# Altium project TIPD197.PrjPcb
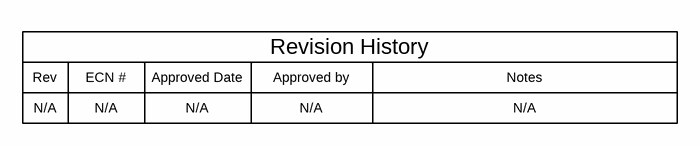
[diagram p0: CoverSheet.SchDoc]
TID: TIPD197; TechSupport: http://e2e.ti.com; SCH_Rev: 0; PRJ_Title: TI Precision Designs; PRJ_Number: TIPD197; PRJ_Engineer: Brian Pisani; PRJ_Customer: Precision Delta Sigma; PCB_Rev: 0; EVM_Orderable: N/A; CopyrightYear: 2015
3 sheets, 32 parts. Net scope: global (net labels, ports and power ports of the same name join across sheets).
Board file: TIPD197.PcbDoc
Sheets:
  CoverSheet.SchDoc
  TID_Hardware.SchDoc
  Front_End_and_ADC.SchDoc

## Sheet CoverSheet.SchDoc
size 431 x 279 mm; Date: Not shown in title block; ApprovedBy: Not shown in title block; CheckedBy: Not shown in title block; Author: Not shown in title block; CompanyName: Not shown in title block; Engineer: Not shown in title block; Organization: Not shown in title block; Address1: Not shown in title block; Address2: Not shown in title block; Address3: Not shown in title block; Address4: Not shown in title block; DocumentNumber: 1; Revision: Use project parameter SCH_Rev; SheetNumber: 1; SheetTotal: 3; PageSetup: Record=PageOptions¦CenterHorizontal=True¦CenterVertical=True¦PrintScale=1.00¦XCorrection=1.00¦YCorrection=1.00¦PrintKind=0¦BorderSize=5000000¦LeftOffset=0¦BottomOffset=0¦Orientation=2¦PaperLength=1000¦PaperWidth=1000¦Scale=100¦PaperSource=15¦PrintQuality=600¦MediaType=1¦DitherType=10¦PaperKind=Letter¦PrintScaleMode=1

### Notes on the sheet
- Rev
- N/A
- ECN #
- Approved Date
- Approved by
- Revision History
- Notes

## Sheet TID_Hardware.SchDoc
size 431 x 279 mm; Date: Not shown in title block; ApprovedBy: Not shown in title block; CheckedBy: Not shown in title block; Author: Not shown in title block; CompanyName: Not shown in title block; Engineer: Not shown in title block; Organization: Not shown in title block; Address1: Not shown in title block; Address2: Not shown in title block; Address3: Not shown in title block; Address4: Not shown in title block; DocumentNumber: 1; Revision: Use project parameter SCH_Rev; SheetNumber: 3; SheetTotal: 3; PageSetup: Record=PageOptions¦CenterHorizontal=True¦CenterVertical=True¦PrintScale=1.00¦XCorrection=1.00¦YCorrection=1.00¦PrintKind=0¦BorderSize=5000000¦LeftOffset=0¦BottomOffset=0¦Orientation=2¦PaperLength=1000¦PaperWidth=1000¦Scale=100¦PaperSource=15¦PrintQuality=600¦MediaType=1¦DitherType=10¦PaperKind=Letter¦PrintScaleMode=1
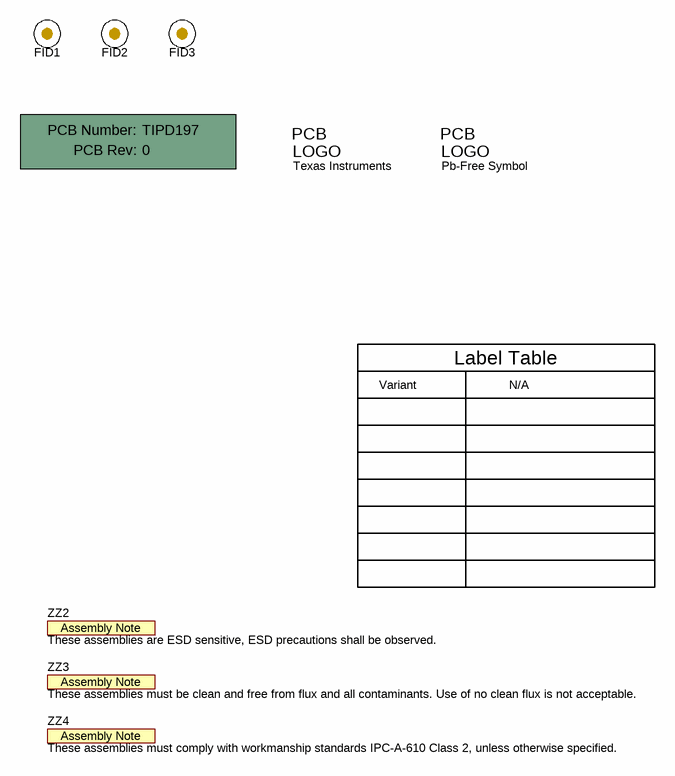
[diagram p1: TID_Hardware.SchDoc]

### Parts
!PCB  Printed Circuit Board  (value not drawn)  (mechanical)
FID1  Fiducial  [Fiducial10-20]  (value not drawn)
FID2  Fiducial  [Fiducial10-20]  (value not drawn)
FID3  Fiducial  [Fiducial10-20]  (value not drawn)
Logo1  Texas Instruments  [TI_Symbol_Overlay_Small]  (no BOM)
Logo2  Pb-Free Symbol  [Pb-Free_Overlay_Small]  (no BOM)
ZZ2  These assemblies are ESD sensitive, ESD precautions shall be observed.  [AssemblyNote]  (no BOM)
ZZ3  These assemblies must be clean and free from flux and all contaminants. Use of no clean flux is not acceptable.  [AssemblyNote]  (no BOM)
ZZ4  These assemblies must comply with workmanship standards IPC-A-610 Class 2, unless otherwise specified.  [AssemblyNote]  (no BOM)

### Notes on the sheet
- Variant
- Label Table
- N/A

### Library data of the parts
!PCB = PCB: Manufacturer: Any; PartNumber: TIPD197; SymbolCreator: a0412235
FID1-FID3 = Fiducial: Fiducial mark.  There is nothing to buy or mount.; SymbolCreator: codlsc
Logo1 = TI_Logo: Texas Instrument Corporate Signature; SymbolCreator: codlsc
Logo2 = Pb-Free: SymbolCreator: a0412235
ZZ2-ZZ4 = AssemblyNote: SymbolCreator: codlsc

## Sheet Front_End_and_ADC.SchDoc: Schematic for TIDCAP1
size 431 x 279 mm; Date: Not shown in title block; ApprovedBy: Not shown in title block; CheckedBy: Not shown in title block; Author: Not shown in title block; CompanyName: Not shown in title block; DrawnBy: Brian Pisani; Engineer: Brian Pisani; Organization: Not shown in title block; Address1: Not shown in title block; Address2: Not shown in title block; Address3: Not shown in title block; Address4: Not shown in title block; DocumentNumber: 1; Revision: Use project parameter SCH_Rev; SheetNumber: 2; SheetTotal: 3; PageSetup: Record=PageOptions¦CenterHorizontal=True¦CenterVertical=True¦PrintScale=1.00¦XCorrection=1.00¦YCorrection=1.00¦PrintKind=0¦BorderSize=5000000¦LeftOffset=0¦BottomOffset=0¦Orientation=2¦PaperLength=1000¦PaperWidth=1000¦Scale=100¦PaperSource=15¦PrintQuality=600¦MediaType=1¦DitherType=10¦PaperKind=Letter¦PrintScaleMode=1
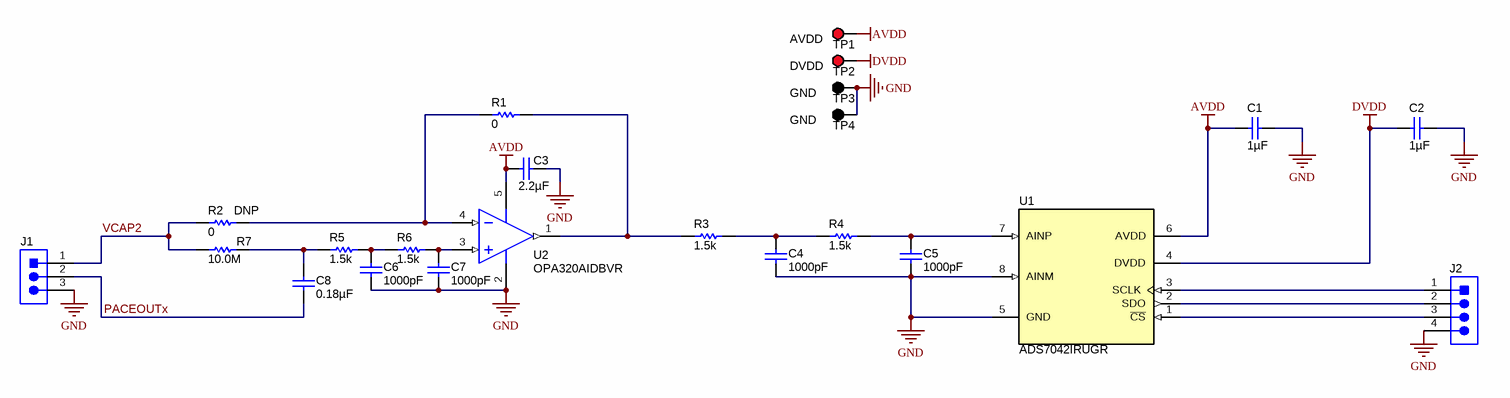
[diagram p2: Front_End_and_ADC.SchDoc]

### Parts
C1  ValueDisplayed: 1µF  [0402]  (hidden comment: C1005X5R1A105K050BB)
C2  ValueDisplayed: 1µF  [0402]  (hidden comment: C1005X5R1A105K050BB)
C3  ValueDisplayed: 2.2µF  [0402]  (hidden comment: C1005X5R1A225K050BC)
C4  ValueDisplayed: 1000pF  [0402]  (hidden comment: GRM155R72A102KA01D)
C5  ValueDisplayed: 1000pF  [0402]  (hidden comment: GRM155R72A102KA01D)
C6  ValueDisplayed: 1000pF  [0402]  (hidden comment: C1005C0G1E102J)
C7  ValueDisplayed: 1000pF  [0402]  (hidden comment: C1005C0G1E102J)
C8  ValueDisplayed: 0.18µF  [0402]  (hidden comment: GRM155R61A184KE19D)
J1  800-10-003-10-001000  [Mill-Max_800-10-003-10-001000]  (value not drawn)
J2  800-10-004-10-001000  [Mill-Max_800-10-004-10-001000]  (value not drawn)
R1  ValueDisplayed: 0  [0402]  (hidden comment: ERJ-2GE0R00X)
R2  DNP  ValueDisplayed: 0  [0402]
R3  ValueDisplayed: 1.5k  [0402]  (hidden comment: CRCW04021K50JNED)
R4  ValueDisplayed: 1.5k  [0402]  (hidden comment: CRCW04021K50JNED)
R5  ValueDisplayed: 1.5k  [0402]  (hidden comment: CRCW04021K50JNED)
R6  ValueDisplayed: 1.5k  [0402]  (hidden comment: CRCW04021K50JNED)
R7  ValueDisplayed: 10.0M  [0402]  (hidden comment: CRCW040210M0FKED)
TP1  AVDD  [Keystone5010]
TP2  DVDD  [Keystone5010]
TP3  GND  [Keystone5011]
TP4  GND  [Keystone5011]
U1  ADS7042IRUGR  [RUG0008A]
U2  OPA320AIDBVR  [DBV0005A_N]

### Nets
AVDD: C1.2 C3.2 TP1.1 U1.6(AVDD) U2.5(V+)
DVDD: C2.2 TP2.1 U1.4(DVDD)
GND: C1.1 C2.1 C3.1 C4.2 C5.2 C6.2 C7.2 J1.3 J2.4 TP3.1 TP4.1 U1.5(GND) U1.8(AINM) U2.2(V-)
PACEOUTx: C8.2 J1.2
VCAP2: J1.1 R2.1 R7.2
NetC4_1: C4.1 R3.2 R4.1
NetC5_1: C5.1 R4.2 U1.7(AINP)
NetC6_1: C6.1 R5.2 R6.1
NetC7_1: C7.1 R6.2 U2.3(IN+)
NetC8_1: C8.1 R5.1 R7.1
NetJ2_1: J2.1 U1.3(SCLK)
NetJ2_2: J2.2 U1.2(SDO)
NetJ2_3: J2.3 U1.1(~{CS})
NetR1_1: R1.1 R2.2 U2.4(IN-)
NetR1_2: R1.2 R3.1 U2.1(OUT)

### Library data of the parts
C1 C2 = C1005X5R1A105K050BB: CAP, CERM, 1 µF, 10 V, +/- 10%, X5R, 0402; Manufacturer: TDK; Polarized: N; CompType: Capacitor; Value: 1uF; U/M: EA; Cap_F: 0.000001; Tolerance_%: 10; Value1: Unknown; Value2: 10V; TaMin_C: -55; TaMax_C: 85
C3 = C1005X5R1A225K050BC: CAP, CERM, 2.2 µF, 10 V, +/- 10%, X5R, 0402; Manufacturer: TDK; Polarized: N; CompType: Capacitor; Value: 2.2uF; U/M: EA; Cap_F: 0.0000022; Tolerance_%: 10; Value1: Unknown; Value2: 10V; TaMin_C: -55; TaMax_C: 85
C4 C5 = GRM155R72A102KA01D: CAP, CERM, 1000 pF, 100 V, +/- 10%, X7R, 0402; Manufacturer: MuRata; Polarized: N; CompType: Capacitor; Value: 1000pF; U/M: EA; Cap_F: 0.000000001; Tolerance_%: 10; Value1: Unknown; VDC_V: 100; Value2: 100V; TaMin_C: -55; TaMax_C: 125
C6 C7 = C1005C0G1E102J: CAP, CERM, 1000 pF, 25 V, +/- 5%, C0G/NP0, 0402; Manufacturer: TDK; Polarized: N; CompType: Capacitor; Value: 1000pF; U/M: EA; Cap_F: 0.000000001; Tolerance_%: 5; Value1: Unknown; VDC_V: 25; Value2: 25V; TaMin_C: -55; TaMax_C: 125
C8 = GRM155R61A184KE19D: CAP, CERM, 0.18 µF, 10 V, +/- 10%, X5R, 0402; Manufacturer: MuRata; Polarized: N; CompType: Capacitor; Value: 0.18uF; U/M: EA; Cap_F: 0.00000018; Tolerance_%: 10; Value1: Unknown; Value2: 10V; TaMin_C: -55; TaMax_C: 85
J1 = 800-10-003-10-001000: Header, 100mil, 3x1, TH; Manufacturer: Mill-Max; SymbolCreator: a0799628; U/M: EA
J2 = 800-10-004-10-001000: Header, 100mil, 4x1, TH; Manufacturer: Mill-Max; SymbolCreator: a0412235; U/M: EA
R1 = ERJ-2GE0R00X: RES, 0, 5%, 0.063 W, 0402; Manufacturer: Panasonic; CompType: Resistor; Value: 0; Value_Code: 0000; Tolerance_%: 5; Power_W: 0.063; Value2: 0.063W; VDC_V: 50; TempCo: 600 ppm/C; EIA_Code: E24; U/M: EA
R2 = CRCW04020000Z0ED: RES, 0, 5%, 0.063 W, 0402; Manufacturer: Vishay-Dale; CompType: Resistor; Value: 0; Value_Code: 0000; Tolerance_%: 5; Power_W: 0.063; Value2: 0.063W; VDC_V: 50; TempCo: 200 ppm/C; EIA_Code: E24; U/M: EA
R3-R6 = CRCW04021K50JNED: RES, 1.5 k, 5%, 0.063 W, 0402; Manufacturer: Vishay-Dale; CompType: Resistor; Value: 1.5k; Res_ohm: 1500; Value_Code: 1k50; Tolerance_%: 5; Power_W: 0.063; Value2: 0.063W; VDC_V: 50; TempCo: 200 ppm/C; EIA_Code: E24; U/M: EA
R7 = CRCW040210M0FKED: RES, 10.0 M, 1%, 0.063 W, 0402; Manufacturer: Vishay-Dale; CompType: Resistor; Value: 10.0Meg; Res_ohm: 10000000; Value_Code: 10M0; Tolerance_%: 1; Power_W: 0.063; Value2: 0.063W; VDC_V: 50; TempCo: 100 ppm/C; EIA_Code: E96; U/M: EA
TP1 TP2 = 5010: Test Point, Multipurpose, Red, TH; Manufacturer: Keystone; CompType: Test Point Loop; U/M: EA
TP3 TP4 = 5011: Test Point, Multipurpose, Black, TH; Manufacturer: Keystone; CompType: Test Point Loop; U/M: EA
U1 = ADS7042IRUGR: Ultra-Low Power, Ultra-Small Size, 12-Bit, 1-MSPS, SAR ADC, RUG0008A; Manufacturer: Texas Instruments; SymbolCreator: Altium; CompType: IC; U/M: EA
U2 = OPA320AIDBVR: Precision, 20 MHz, 0.9 pA Ib, RRIO, CMOS Operational Amplifier, 1.8 to 5.5 V, -40 to 125 degC, 5-pin SOT23 (DBV0005A), Green (RoHS & no Sb/Br); Manufacturer: Texas Instruments; Alternate Manufacturer: None; Alternate PartNumber: Equivalent; CMRR(Min)(dB): 100; IIB(Max)(pA): 0.9; Iq per channel(Max)(mA): 1.75; Number of Channels: 2; Offset Drift(Typ)(uV/C): 1.5; Slew Rate(Typ)(V/us): 10; Sub Family: High Output Current Amplifier (>=50mA), Low Input Bias Current Amp (<=10pA), Low Noise Amp (<=10nV/rtHz), Low Offset Voltage Amplifier (<=500uV), Low Supply Voltage Amplifier (<=2.7V), Precision Amplifier; Total Supply Voltage(Max)(+5V is 5, +/-5V is 10): 5.5; Total Supply Voltage(Min)(+5V is 5, +/-5V is 10): 1.8; Vio (25C)(Max)(mV): 0.15; Vn at 1kHz(Typ)(nV/rtHz): 8.5

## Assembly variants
001: not fitted FID1 FID2 FID3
